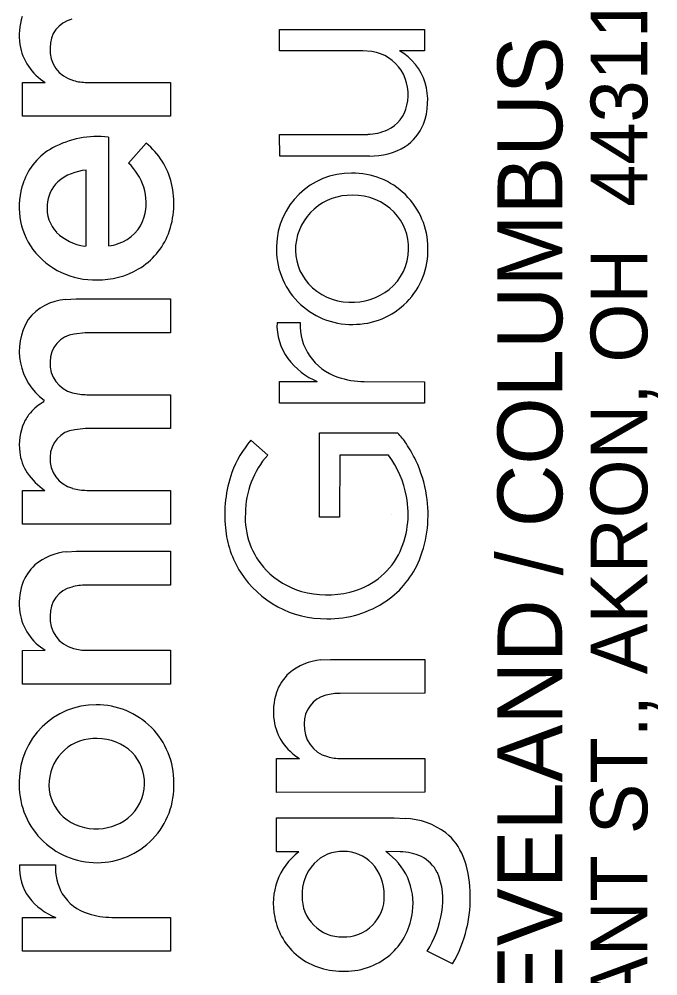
# Model space of a CAD drawing. Extents: x 0 to 63.6, y 0 to 22.
# Drawn here: x 32.423 to 32.984, y 3.594 to 4.436 of the extents above; entities that cross this region are included whole.
import ezdxf

# ---------------------------------------------------------------- set-up
doc = ezdxf.new("R2010")
doc.units = 0
doc.layers.add('SH_Data', color=7, linetype='Continuous')

msp = doc.modelspace()

# ---------------------------------------------------------------- linework, layer by layer
at = {"layer": 'SH_Data'}
for p, q in [((32.65152, 4.40801), (32.65153, 4.42672)), ((32.65153, 4.42672), (32.7791, 4.42664)), ((32.7791, 4.42664), (32.77908, 4.40796)), ((32.7249, 4.40796), (32.65152, 4.40801)), ((32.7328, 4.40727), (32.7249, 4.40796)), ((32.77908, 4.40796), (32.75689, 4.40796)), ((32.42542, 4.38016), (32.44552, 4.38021)), ((32.42542, 4.35035), (32.42542, 4.38016)), ((32.48222, 4.38021), (32.55569, 4.38021)), ((32.55569, 4.38021), (32.55571, 4.35045)), ((32.55571, 4.35045), (32.42542, 4.35035)), ((32.65154, 4.33443), (32.72905, 4.3345)), ((32.65165, 4.31543), (32.65154, 4.33443)), ((32.50108, 4.33209), (32.50118, 4.23657)), ((32.51882, 4.30927), (32.53422, 4.32662)), ((32.73073, 4.31543), (32.65165, 4.31543)), ((32.48144, 4.23644), (32.48144, 4.30296)), ((32.48016, 4.23628), (32.48144, 4.23644)), ((32.46329, 4.18915), (32.47259, 4.18968)), ((32.47259, 4.18968), (32.55557, 4.18968)), ((32.55557, 4.18968), (32.55571, 4.15982)), ((32.64932, 4.16907), (32.66978, 4.16907)), ((32.48058, 4.15981), (32.47102, 4.15881)), ((32.55571, 4.15982), (32.48058, 4.15981)), ((32.65152, 4.11699), (32.68476, 4.117)), ((32.65152, 4.098), (32.65152, 4.11699)), ((32.72605, 4.11703), (32.7791, 4.11696)), ((32.7791, 4.11696), (32.77903, 4.098)), ((32.44443, 4.09922), (32.44455, 4.10072)), ((32.48218, 4.10553), (32.55571, 4.10548)), ((32.55571, 4.10548), (32.55571, 4.07568)), ((32.77903, 4.098), (32.65152, 4.098)), ((32.4809, 4.07567), (32.47143, 4.07474)), ((32.55571, 4.07568), (32.4809, 4.07567)), ((32.62636, 4.06548), (32.64114, 4.05241)), ((32.6868, 4.07185), (32.75516, 4.07192)), ((32.6868, 3.99778), (32.6868, 4.07185)), ((32.70448, 4.05241), (32.70432, 3.99775)), ((32.74737, 4.05227), (32.70448, 4.05241)), ((32.42542, 3.99152), (32.42545, 4.02138)), ((32.42545, 4.02138), (32.44515, 4.02138)), ((32.48206, 4.02138), (32.55571, 4.02136)), ((32.55571, 4.02136), (32.55571, 3.99156)), ((32.70432, 3.99775), (32.6868, 3.99778)), ((32.75, 4), (32.75, 4)), ((32.55571, 3.99156), (32.42542, 3.99152)), ((32.46439, 3.96736), (32.47289, 3.96783)), ((32.47289, 3.96783), (32.55571, 3.96783)), ((32.55571, 3.96783), (32.55571, 3.93804)), ((32.55571, 3.93804), (32.4814, 3.93796)), ((32.42542, 3.88066), (32.44552, 3.88071)), ((32.42542, 3.85086), (32.42542, 3.88066)), ((32.48222, 3.88071), (32.55569, 3.88071)), ((32.55569, 3.88071), (32.55571, 3.85096)), ((32.68784, 3.8722), (32.69634, 3.87266)), ((32.69634, 3.87266), (32.77916, 3.87266)), ((32.77916, 3.87266), (32.77917, 3.84287)), ((32.55571, 3.85096), (32.42542, 3.85086)), ((32.77917, 3.84287), (32.70485, 3.8428)), ((32.64888, 3.7855), (32.66897, 3.78555)), ((32.64888, 3.75569), (32.64888, 3.7855)), ((32.70568, 3.78555), (32.77915, 3.78555)), ((32.77915, 3.78555), (32.77917, 3.75579)), ((32.77917, 3.75579), (32.64888, 3.75569)), ((32.6489, 3.70336), (32.64889, 3.73322)), ((32.64889, 3.73322), (32.75236, 3.73322)), ((32.75236, 3.73322), (32.76191, 3.73285)), ((32.66836, 3.70336), (32.6489, 3.70336)), ((32.75763, 3.70356), (32.74487, 3.70361)), ((32.42299, 3.69193), (32.45454, 3.69193)), ((32.42542, 3.64577), (32.45473, 3.64579)), ((32.42542, 3.61593), (32.42542, 3.64577)), ((32.50413, 3.64581), (32.55571, 3.64573)), ((32.55571, 3.64573), (32.55565, 3.61593)), ((32.55565, 3.61593), (32.42542, 3.61593)), ((32.8036, 3.60491), (32.7812, 3.61598))]:
    msp.add_line(p, q, dxfattribs=at)
for points in [[(32.7328, 4.40727), (32.7249, 4.40796), (32.65152, 4.40801), (32.65153, 4.42672), (32.7791, 4.42664), (32.77908, 4.40796), (32.75689, 4.40796)], [(32.42542, 4.35035), (32.42542, 4.38016), (32.44552, 4.38021)], [(32.48222, 4.38021), (32.55569, 4.38021), (32.55571, 4.35045), (32.42542, 4.35035)], [(32.73073, 4.31543), (32.65165, 4.31543), (32.65154, 4.33443), (32.72905, 4.3345)], [(32.50108, 4.33209), (32.50118, 4.23657)], [(32.51882, 4.30927), (32.53422, 4.32662)], [(32.48016, 4.23628), (32.48144, 4.23644), (32.48144, 4.30296)], [(32.46329, 4.18915), (32.47259, 4.18968), (32.55557, 4.18968), (32.55571, 4.15982), (32.48058, 4.15981), (32.47102, 4.15881)], [(32.64932, 4.16907), (32.66978, 4.16907)], [(32.72605, 4.11703), (32.7791, 4.11696), (32.77903, 4.098), (32.65152, 4.098)], [(32.65152, 4.098), (32.65152, 4.11699), (32.68476, 4.117)], [(32.44443, 4.09922), (32.44455, 4.10072)], [(32.48218, 4.10553), (32.55571, 4.10548), (32.55571, 4.07568), (32.4809, 4.07567), (32.47143, 4.07474)], [(32.62636, 4.06548), (32.64114, 4.05241)], [(32.74737, 4.05227), (32.70448, 4.05241), (32.70432, 3.99775), (32.6868, 3.99778), (32.6868, 4.07185), (32.75516, 4.07192)], [(32.42542, 3.99152), (32.42545, 4.02138), (32.44515, 4.02138)], [(32.48206, 4.02138), (32.55571, 4.02136), (32.55571, 3.99156), (32.42542, 3.99152)], [(32.46439, 3.96736), (32.47289, 3.96783), (32.55571, 3.96783), (32.55571, 3.93804), (32.4814, 3.93796)], [(32.42542, 3.85086), (32.42542, 3.88066), (32.44552, 3.88071)], [(32.48222, 3.88071), (32.55569, 3.88071), (32.55571, 3.85096), (32.42542, 3.85086)], [(32.68784, 3.8722), (32.69634, 3.87266), (32.77916, 3.87266), (32.77917, 3.84287), (32.70485, 3.8428)], [(32.64888, 3.75569), (32.64888, 3.7855), (32.66897, 3.78555)], [(32.70568, 3.78555), (32.77915, 3.78555), (32.77917, 3.75579), (32.64888, 3.75569)], [(32.66836, 3.70336), (32.6489, 3.70336), (32.64889, 3.73322), (32.75236, 3.73322), (32.76191, 3.73285)], [(32.75763, 3.70356), (32.74487, 3.70361)], [(32.42299, 3.69193), (32.45454, 3.69193)], [(32.50413, 3.64581), (32.55571, 3.64573), (32.55565, 3.61593), (32.42542, 3.61593)], [(32.42542, 3.61593), (32.42542, 3.64577), (32.45473, 3.64579)], [(32.8036, 3.60491), (32.7812, 3.61598)]]:
    msp.add_lwpolyline(points, dxfattribs=at)
for centre, radius, start, end in [((32.47872, 4.42108), 0.05602, 162.27398, 187.79173), ((32.47872, 4.42108), 0.05602, 162.27398, 187.79173), ((32.47482, 4.41155), 0.02498, 103.68683, 182.21395), ((32.47482, 4.41155), 0.02498, 103.68683, 182.21395), ((32.47027, 4.4209), 0.04763, 188.96462, 238.69865), ((32.47027, 4.4209), 0.04763, 188.96462, 238.69865), ((32.47735, 4.40846), 0.02757, 175.58441, 255.13816), ((32.47735, 4.40846), 0.02757, 175.58441, 255.13816), ((32.72711, 4.36998), 0.03772, 33.50082, 81.32954), ((32.72711, 4.36998), 0.03772, 33.50082, 81.32954), ((32.73239, 4.36485), 0.04959, 17.62209, 60.38974), ((32.73239, 4.36485), 0.04959, 17.62209, 60.38974), ((32.72414, 4.3695), 0.04048, 346.56179, 31.75389), ((32.72414, 4.3695), 0.04048, 346.56179, 31.75389), ((32.48183, 4.42235), 0.04215, 254.08913, 270.52838), ((32.48183, 4.42235), 0.04215, 254.08913, 270.52838), ((32.72343, 4.36415), 0.05838, 339.16197, 15.61485), ((32.72343, 4.36415), 0.05838, 339.16197, 15.61485), ((32.73371, 4.36616), 0.03042, 294.63214, 348.48625), ((32.73371, 4.36616), 0.03042, 294.63214, 348.48625), ((32.739, 4.35901), 0.04201, 303.10391, 338.15613), ((32.739, 4.35901), 0.04201, 303.10391, 338.15613), ((32.72747, 4.38081), 0.04633, 271.95199, 294.08943), ((32.72747, 4.38081), 0.04633, 271.95199, 294.08943), ((32.49176, 4.24874), 0.08387, 83.62118, 118.28448), ((32.49176, 4.24874), 0.08387, 83.62118, 118.28448), ((32.49399, 4.2763), 0.06443, 13.53275, 51.36266), ((32.49399, 4.2763), 0.06443, 13.53275, 51.36266), ((32.47894, 4.27368), 0.05583, 118.82935, 160.62242), ((32.47894, 4.27368), 0.05583, 118.82935, 160.62242), ((32.7321, 4.37256), 0.05715, 268.62699, 301.47779), ((32.7321, 4.37256), 0.05715, 268.62699, 301.47779), ((32.48033, 4.27018), 0.05485, 19.0387, 45.44322), ((32.48033, 4.27018), 0.05485, 19.0387, 45.44322), ((32.4844, 4.26071), 0.04236, 94.01311, 130.88062), ((32.4844, 4.26071), 0.04236, 94.01311, 130.88062), ((32.71435, 4.23484), 0.06552, 89.48213, 178.77752), ((32.71435, 4.23484), 0.06552, 89.48213, 178.77752), ((32.71582, 4.23414), 0.06623, 0.42265, 90.7613), ((32.71582, 4.23414), 0.06623, 0.42265, 90.7613), ((32.48697, 4.27074), 0.06438, 160.52138, 215.78155), ((32.48697, 4.27074), 0.06438, 160.52138, 215.78155), ((32.47703, 4.2709), 0.02985, 132.98553, 177.1802), ((32.47703, 4.2709), 0.02985, 132.98553, 177.1802), ((32.48724, 4.27433), 0.04701, 344.60723, 17.00675), ((32.48724, 4.27433), 0.04701, 344.60723, 17.00675), ((32.48289, 4.27384), 0.0758, 339.35431, 13.37708), ((32.48289, 4.27384), 0.0758, 339.35431, 13.37708), ((32.71397, 4.23244), 0.04846, 87.68827, 175.01696), ((32.71397, 4.23244), 0.04846, 87.68827, 175.01696), ((32.71659, 4.23036), 0.05052, 44.91202, 90.75914), ((32.71659, 4.23036), 0.05052, 44.91202, 90.75914), ((32.47824, 4.26966), 0.03114, 175.00138, 223.2876), ((32.47824, 4.26966), 0.03114, 175.00138, 223.2876), ((32.49895, 4.27177), 0.03504, 288.01084, 343.55364), ((32.49895, 4.27177), 0.03504, 288.01084, 343.55364), ((32.71955, 4.23452), 0.04549, 358.32279, 43.83486), ((32.71955, 4.23452), 0.04549, 358.32279, 43.83486), ((32.48546, 4.27826), 0.04232, 225.06454, 262.79701), ((32.48546, 4.27826), 0.04232, 225.06454, 262.79701), ((32.49548, 4.26982), 0.0626, 300.94393, 338.73223), ((32.49548, 4.26982), 0.0626, 300.94393, 338.73223), ((32.48908, 4.27516), 0.06872, 217.74341, 271.65606), ((32.48908, 4.27516), 0.06872, 217.74341, 271.65606), ((32.50129, 4.25678), 0.02021, 269.70042, 294.87295), ((32.50129, 4.25678), 0.02021, 269.70042, 294.87295), ((32.71483, 4.2334), 0.06606, 177.53728, 270.94524), ((32.71483, 4.2334), 0.06606, 177.53728, 270.94524), ((32.71085, 4.23311), 0.0453, 175.51467, 221.42047), ((32.71085, 4.23311), 0.0453, 175.51467, 221.42047), ((32.71671, 4.23271), 0.06536, 269.30834, 1.67905), ((32.71671, 4.23271), 0.06536, 269.30834, 1.67905), ((32.71931, 4.23374), 0.04572, 308.90382, 359.30947), ((32.71931, 4.23374), 0.04572, 308.90382, 359.30947), ((32.49204, 4.27702), 0.07055, 269.20529, 300.33566), ((32.49204, 4.27702), 0.07055, 269.20529, 300.33566), ((32.71399, 4.23734), 0.05046, 222.66255, 268.37331), ((32.71399, 4.23734), 0.05046, 222.66255, 268.37331), ((32.71567, 4.23859), 0.05178, 266.55312, 308.67253), ((32.71567, 4.23859), 0.05178, 266.55312, 308.67253), ((32.46638, 4.14404), 0.04521, 93.91118, 142.30723), ((32.46638, 4.14404), 0.04521, 93.91118, 142.30723), ((32.47585, 4.14373), 0.05319, 148.28793, 233.9556), ((32.47585, 4.14373), 0.05319, 148.28793, 233.9556), ((32.69878, 4.16662), 0.04952, 177.16211, 216.28024), ((32.69878, 4.16662), 0.04952, 177.16211, 216.28024), ((32.71735, 4.16638), 0.04764, 176.76988, 252.15044), ((32.71735, 4.16638), 0.04764, 176.76988, 252.15044), ((32.47384, 4.13499), 0.02399, 96.75763, 181.6251), ((32.47384, 4.13499), 0.02399, 96.75763, 181.6251), ((32.47577, 4.13241), 0.02597, 175.81573, 256.16716), ((32.47577, 4.13241), 0.02597, 175.81573, 256.16716), ((32.70975, 4.17555), 0.06366, 216.91526, 246.88619), ((32.70975, 4.17555), 0.06366, 216.91526, 246.88619), ((32.7269, 4.19175), 0.07473, 251.13884, 269.34694), ((32.7269, 4.19175), 0.07473, 251.13884, 269.34694), ((32.4817, 4.15053), 0.04501, 254.34629, 270.61033), ((32.4817, 4.15053), 0.04501, 254.34629, 270.61033), ((32.4638, 4.06267), 0.04137, 117.91625, 139.24296), ((32.4638, 4.06267), 0.04137, 117.91625, 139.24296), ((32.46194, 4.06452), 0.03875, 139.52447, 154.84698), ((32.46194, 4.06452), 0.03875, 139.52447, 154.84698), ((32.47144, 4.0612), 0.04877, 156.06382, 187.3493), ((32.47144, 4.0612), 0.04877, 156.06382, 187.3493), ((32.47421, 4.05056), 0.02434, 96.5532, 179.94902), ((32.47421, 4.05056), 0.02434, 96.5532, 179.94902), ((32.70163, 4.00187), 0.09855, 139.79476, 159.13696), ((32.70163, 4.00187), 0.09855, 139.79476, 159.13696), ((32.72498, 4.03937), 0.04438, 30.98913, 47.16099), ((32.72498, 4.03937), 0.04438, 30.98913, 47.16099), ((32.67091, 4.00018), 0.11106, 25.30315, 33.96179), ((32.67091, 4.00018), 0.11106, 25.30315, 33.96179), ((32.46461, 4.05974), 0.04181, 186.5579, 213.38846), ((32.46461, 4.05974), 0.04181, 186.5579, 213.38846), ((32.47608, 4.04863), 0.02628, 175.722, 255.78627), ((32.47608, 4.04863), 0.02628, 175.722, 255.78627), ((32.69899, 4.00079), 0.07753, 138.25804, 179.70064), ((32.69899, 4.00079), 0.07753, 138.25804, 179.70064), ((32.67889, 4.00099), 0.08556, 10.07509, 36.83189), ((32.67889, 4.00099), 0.08556, 10.07509, 36.83189), ((32.6704, 3.99987), 0.11166, 8.80339, 25.33484), ((32.6704, 3.99987), 0.11166, 8.80339, 25.33484), ((32.47886, 4.07078), 0.0598, 214.70433, 235.68724), ((32.47886, 4.07078), 0.0598, 214.70433, 235.68724), ((32.7187, 3.99968), 0.11536, 161.14379, 185.62812), ((32.7187, 3.99968), 0.11536, 161.14379, 185.62812), ((32.48195, 4.06518), 0.0438, 253.66719, 270.14979), ((32.48195, 4.06518), 0.0438, 253.66719, 270.14979), ((32.68425, 4.00057), 0.08036, 333.46689, 11.03668), ((32.68425, 4.00057), 0.08036, 333.46689, 11.03668), ((32.67564, 3.99977), 0.10649, 338.28866, 9.28548), ((32.67564, 3.99977), 0.10649, 338.28866, 9.28548), ((32.68811, 3.99732), 0.06676, 176.66577, 223.6912), ((32.68811, 3.99732), 0.06676, 176.66577, 223.6912), ((32.69336, 3.99699), 0.08987, 185.50773, 212.01294), ((32.69336, 3.99699), 0.08987, 185.50773, 212.01294), ((32.46871, 3.91767), 0.04988, 94.97056, 130.22484), ((32.46871, 3.91767), 0.04988, 94.97056, 130.22484), ((32.69868, 3.99547), 0.0652, 282.88151, 331.81475), ((32.69868, 3.99547), 0.0652, 282.88151, 331.81475), ((32.46348, 3.92602), 0.04016, 132.22383, 161.68229), ((32.46348, 3.92602), 0.04016, 132.22383, 161.68229), ((32.69835, 3.99168), 0.08241, 305.03061, 337.67573), ((32.69835, 3.99168), 0.08241, 305.03061, 337.67573), ((32.69211, 3.99748), 0.08908, 212.70222, 270.71399), ((32.69211, 3.99748), 0.08908, 212.70222, 270.71399), ((32.69045, 4.00011), 0.07039, 224.02147, 253.88), ((32.69045, 4.00011), 0.07039, 224.02147, 253.88), ((32.47872, 3.92158), 0.05602, 162.27398, 187.79173), ((32.47872, 3.92158), 0.05602, 162.27398, 187.79173), ((32.47482, 3.91206), 0.02498, 103.68683, 182.21395), ((32.47482, 3.91206), 0.02498, 103.68683, 182.21395), ((32.48108, 3.89196), 0.04601, 89.60515, 105.33026), ((32.48108, 3.89196), 0.04601, 89.60515, 105.33026), ((32.69318, 4.01254), 0.08309, 254.45353, 283.9512), ((32.69318, 4.01254), 0.08309, 254.45353, 283.9512), ((32.69429, 3.99979), 0.09138, 269.3273, 304.19632), ((32.69429, 3.99979), 0.09138, 269.3273, 304.19632), ((32.47027, 3.92141), 0.04763, 188.96462, 238.69865), ((32.47027, 3.92141), 0.04763, 188.96462, 238.69865), ((32.47735, 3.90897), 0.02757, 175.58441, 255.13816), ((32.47735, 3.90897), 0.02757, 175.58441, 255.13816), ((32.48183, 3.92286), 0.04215, 254.08913, 270.52838), ((32.48183, 3.92286), 0.04215, 254.08913, 270.52838), ((32.69216, 3.82251), 0.04988, 94.97056, 130.22484), ((32.69216, 3.82251), 0.04988, 94.97056, 130.22484), ((32.68694, 3.83085), 0.04016, 132.22383, 161.68229), ((32.68694, 3.83085), 0.04016, 132.22383, 161.68229), ((32.70217, 3.82642), 0.05602, 162.27398, 187.79173), ((32.70217, 3.82642), 0.05602, 162.27398, 187.79173), ((32.69828, 3.81689), 0.02498, 103.68683, 182.21395), ((32.69828, 3.81689), 0.02498, 103.68683, 182.21395), ((32.70453, 3.79679), 0.04601, 89.60515, 105.33026), ((32.70453, 3.79679), 0.04601, 89.60515, 105.33026), ((32.49014, 3.76543), 0.0674, 89.84756, 179.64047), ((32.49014, 3.76543), 0.0674, 89.84756, 179.64047), ((32.49057, 3.76474), 0.0681, 359.54009, 90.21138), ((32.49057, 3.76474), 0.0681, 359.54009, 90.21138), ((32.69372, 3.82624), 0.04763, 188.96462, 238.69865), ((32.69372, 3.82624), 0.04763, 188.96462, 238.69865), ((32.7008, 3.81381), 0.02757, 175.58441, 255.13816), ((32.7008, 3.81381), 0.02757, 175.58441, 255.13816), ((32.48923, 3.76263), 0.0404, 87.04809, 175.57259), ((32.48923, 3.76263), 0.0404, 87.04809, 175.57259), ((32.49204, 3.75999), 0.04299, 45.84264, 90.98008), ((32.49204, 3.75999), 0.04299, 45.84264, 90.98008), ((32.49458, 3.76421), 0.03821, 357.88569, 44.15902), ((32.49458, 3.76421), 0.03821, 357.88569, 44.15902), ((32.70529, 3.82769), 0.04215, 254.08913, 270.52838), ((32.70529, 3.82769), 0.04215, 254.08913, 270.52838), ((32.49083, 3.76209), 0.06819, 176.8344, 270.40384), ((32.49083, 3.76209), 0.06819, 176.8344, 270.40384), ((32.48729, 3.7625), 0.03848, 175.15378, 221.14706), ((32.48729, 3.7625), 0.03848, 175.15378, 221.14706), ((32.49123, 3.76139), 0.06749, 270.06243, 2.37759), ((32.49123, 3.76139), 0.06749, 270.06243, 2.37759), ((32.49446, 3.76318), 0.0383, 308.28936, 359.43468), ((32.49446, 3.76318), 0.0383, 308.28936, 359.43468), ((32.48919, 3.76607), 0.04228, 223.09994, 268.80895), ((32.48919, 3.76607), 0.04228, 223.09994, 268.80895), ((32.49096, 3.7679), 0.04418, 266.56515, 308.06078), ((32.49096, 3.7679), 0.04418, 266.56515, 308.06078), ((32.75907, 3.66789), 0.06503, 53.40344, 87.49062), ((32.75907, 3.66789), 0.06503, 53.40344, 87.49062), ((32.76517, 3.68039), 0.05141, 21.60748, 50.5577), ((32.76517, 3.68039), 0.05141, 21.60748, 50.5577), ((32.70292, 3.65813), 0.05692, 127.37482, 192.22468), ((32.70292, 3.65813), 0.05692, 127.37482, 192.22468), ((32.70693, 3.66927), 0.0346, 88.47302, 136.42562), ((32.70693, 3.66927), 0.0346, 88.47302, 136.42562), ((32.70814, 3.66963), 0.03424, 44.27195, 90.47623), ((32.70814, 3.66963), 0.03424, 44.27195, 90.47623), ((32.71421, 3.65829), 0.05472, 352.1125, 55.92295), ((32.71421, 3.65829), 0.05472, 352.1125, 55.92295), ((32.75666, 3.65725), 0.04633, 65.01687, 88.8011), ((32.75666, 3.65725), 0.04633, 65.01687, 88.8011), ((32.7626, 3.67155), 0.03085, 26.26808, 63.80301), ((32.7626, 3.67155), 0.03085, 26.26808, 63.80301), ((32.73069, 3.66714), 0.08835, 1.15143, 21.3627), ((32.73069, 3.66714), 0.08835, 1.15143, 21.3627), ((32.46616, 3.68882), 0.04329, 175.87313, 216.34747), ((32.46616, 3.68882), 0.04329, 175.87313, 216.34747), ((32.50087, 3.68948), 0.04639, 176.9688, 209.60636), ((32.50087, 3.68948), 0.04639, 176.9688, 209.60636), ((32.71141, 3.66602), 0.0401, 137.46739, 182.33237), ((32.71141, 3.66602), 0.0401, 137.46739, 182.33237), ((32.70368, 3.666), 0.03996, 358.57141, 43.53765), ((32.70368, 3.666), 0.03996, 358.57141, 43.53765), ((32.73565, 3.66154), 0.05953, 349.30734, 23.43071), ((32.73565, 3.66154), 0.05953, 349.30734, 23.43071), ((32.70538, 3.66244), 0.11383, 329.6388, 3.25998), ((32.70538, 3.66244), 0.11383, 329.6388, 3.25998), ((32.47466, 3.69716), 0.05511, 218.09809, 248.7907), ((32.47466, 3.69716), 0.05511, 218.09809, 248.7907), ((32.49514, 3.68814), 0.04079, 211.94466, 253.2028), ((32.49514, 3.68814), 0.04079, 211.94466, 253.2028), ((32.70645, 3.6637), 0.03511, 178.88208, 271.08374), ((32.70645, 3.6637), 0.03511, 178.88208, 271.08374), ((32.70818, 3.66404), 0.03546, 268.27882, 1.55016), ((32.70818, 3.66404), 0.03546, 268.27882, 1.55016), ((32.50465, 3.7165), 0.07069, 252.46555, 269.57296), ((32.50465, 3.7165), 0.07069, 252.46555, 269.57296), ((32.70463, 3.65696), 0.05837, 190.75182, 231.28919), ((32.70463, 3.65696), 0.05837, 190.75182, 231.28919), ((32.70988, 3.65708), 0.05887, 313.74196, 353.8554), ((32.70988, 3.65708), 0.05887, 313.74196, 353.8554), ((32.70738, 3.66334), 0.08771, 327.31495, 351.57478), ((32.70738, 3.66334), 0.08771, 327.31495, 351.57478), ((32.70632, 3.66112), 0.06269, 232.46061, 272.59022), ((32.70632, 3.66112), 0.06269, 232.46061, 272.59022), ((32.70954, 3.65901), 0.06051, 269.6361, 312.70877), ((32.70954, 3.65901), 0.06051, 269.6361, 312.70877)]:
    msp.add_arc(centre, radius, start, end, dxfattribs=at)

# ---------------------------------------------------------------- texts
for s, height, p in [('450 GRANT ST., AKRON, OH  44311', 0.0498462, (32.97489, 3.33738)), ('AKRON / CLEVELAND / COLUMBUS', 0.056969, (32.90012, 3.138))]:
    msp.add_text(s, height=height, rotation=90, dxfattribs=at).set_placement(p)

doc.saveas('drawing.dxf')
